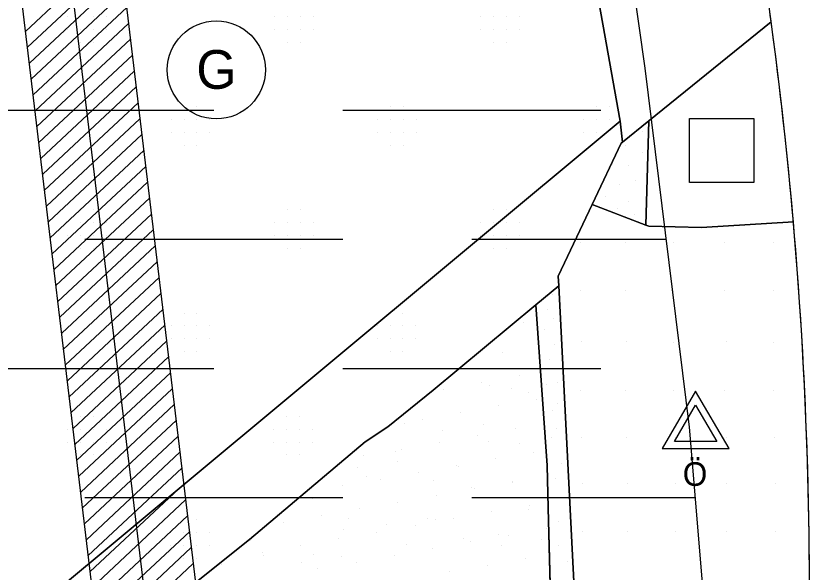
# Model space of a CAD drawing. Extents: x 409341 to 428634, y 4447481 to 4463281.
# Drawn here: x 420055.7 to 420363.5, y 4458027.9 to 4458243.5 of the extents above; entities that cross this region are included whole.
import ezdxf

# ---------------------------------------------------------------- set-up
doc = ezdxf.new("R2010")
doc.units = 0
for name, color, linetype in [('ADA', 7, 'Continuous'), ('ADAKENARI', 7, 'Continuous'), ('Default', 7, 'Continuous'), ('KALDIRIM', 7, 'Continuous'), ('LJ_SEMBOL', 7, 'Continuous'), ('PL_AYA_PARK_DINLENME', 7, 'Continuous'), ('PL_EĞİTİM', 7, 'Continuous'), ('PL_K_AKARYAKIT_LPG_Y', 7, 'Continuous'), ('PL_K_K_D_K_C_A', 7, 'Continuous'), ('PL_T_GUNUBIRLIK', 7, 'Continuous'), ('SEMBOL', 7, 'Continuous'), ('SN_TASKIN', 7, 'Continuous'), ('SN_TR_TASKIN', 7, 'Continuous'), ('TA_ENH_154', 7, 'Continuous'), ('TA_ENH_KORUMA', 7, 'Continuous'), ('TA_ENH_TARAMA', 7, 'Continuous'), ('TR_AKARYAKIT_SERVİS', 7, 'Continuous'), ('TR_BAKIMAKARYAKIT', 7, 'Continuous'), ('TR_EĞİTİM', 7, 'Continuous'), ('TR_KONUTDISIKCA', 7, 'Continuous'), ('TR_PARKALANI', 7, 'Continuous'), ('TR_TURIZM', 7, 'Continuous')]:
    doc.layers.add(name, color=color, linetype=linetype)

# ---------------------------------------------------------------- blocks, each defined once
blk = doc.blocks.new('POINT_DISPLAY')
at = {"layer": 'Default'}
blk.add_line((0, 0), (0, 0), dxfattribs=at)

msp = doc.modelspace()

# ---------------------------------------------------------------- linework, layer by layer
at = {"layer": 'ADA'}
for p, q in [((420289.84, 4458202.73), (420262.42, 4458356.84)), ((420289.84, 4458202.73), (420054.04, 4458006.23)), ((420290.78, 4458194.57), (420289.84, 4458202.73))]:
    msp.add_line(p, q, dxfattribs=at)
at = {"layer": 'ADAKENARI'}
for p, q in [((420300.95, 4458202.79), (420348.42, 4458241.16)), ((420290.78, 4458194.57), (420300.95, 4458202.79)), ((420300.95, 4458202.79), (420299.88, 4458162.44)), ((420279.04, 4458170.41), (420290.28, 4458194.16)), ((420290.28, 4458194.16), (420290.78, 4458194.57)), ((420299.88, 4458162.44), (420279.04, 4458170.41))]:
    msp.add_line(p, q, dxfattribs=at)
for points in [[(420279.04, 4458170.41), (420265.92, 4458142.64), (420273.08, 4458001.35), (420328.98, 4457995.17), (420362.93, 4457988.11)], [(420299.88, 4458162.44), (420301, 4458162.02), (420321.4, 4458161.48), (420357.02, 4458163.71)], [(420257.25, 4458131.54), (420266.1, 4458138.91)], [(420016.48, 4457954.29), (420055.68, 4457954.88), (420067.57, 4457974.09), (420078.76, 4457985.69), (420086.67, 4457992.9), (420092.78, 4457997.85), (420146.22, 4458040.56), (420191.1, 4458078.42), (420199.8, 4458084.26), (420217.45, 4458098.42), (420257.25, 4458131.54)], [(420140.13, 4457983.98), (420152.2, 4457903.36), (420230.46, 4457896.72), (420265.95, 4457891.84), (420263.49, 4457993.09), (420262.04, 4458052.83), (420261.63, 4458069.31), (420257.25, 4458131.54)]]:
    msp.add_lwpolyline(points, dxfattribs=at)
msp.add_arc((418713.25, 4458020.48), 1650, 356.27481, 10.61036, dxfattribs=at)
at = {"layer": 'KALDIRIM'}
msp.add_arc((418710.91, 4458046.13), 1668.19, 355.40061, 10.30342, dxfattribs=at)
msp.add_arc((418710.91, 4458046.13), 1668.19, 355.40061, 10.30342, dxfattribs=at)
at = {"layer": 'LJ_SEMBOL'}
for points in [[(420332.08, 4458075.78), (420319.14, 4458098.1), (420306.2, 4458075.78), (420332.08, 4458075.78)], [(420319.14, 4458092.62), (420327.31, 4458078.53), (420310.97, 4458078.53), (420319.14, 4458092.62)]]:
    msp.add_lwpolyline(points, dxfattribs=at)
msp.add_circle((420133.39, 4458222.56), 19, dxfattribs=at)
at = {"layer": 'PL_AYA_PARK_DINLENME'}
for points in [[(420300.95, 4458202.79), (420290.78, 4458194.57), (420290.28, 4458194.16), (420279.04, 4458170.41), (420299.88, 4458162.44), (420300.95, 4458202.79)], [(420263.35, 4457998.86), (420268, 4458006.76), (420273.08, 4458001.35), (420266.1, 4458138.91), (420257.25, 4458131.54), (420261.63, 4458069.31), (420262.04, 4458052.83), (420263.35, 4457998.86)], [(420041.95, 4457909.49), (420140.13, 4457983.98), (420173.45, 4458009.25), (420263.49, 4457993.09), (420262.04, 4458052.83), (420261.63, 4458069.31), (420257.25, 4458131.54), (420217.45, 4458098.42), (420199.8, 4458084.26), (420191.1, 4458078.42), (420146.22, 4458040.56), (420092.78, 4457997.85), (420086.67, 4457992.9), (420078.76, 4457985.69), (420067.57, 4457974.09), (420055.68, 4457954.88)]]:
    msp.add_lwpolyline(points, dxfattribs=at)
at = {"layer": 'PL_EĞİTİM'}
msp.add_lwpolyline([(420357.02, 4458163.71), (420321.4, 4458161.48), (420301, 4458162.02), (420299.88, 4458162.44), (420279.04, 4458170.41), (420265.92, 4458142.64), (420266.1, 4458138.91), (420273.08, 4458001.35), (420328.98, 4457995.17), (420362.93, 4457988.11)], dxfattribs=at)
msp.add_arc((418713.25, 4458020.48), 1650, 358.87612, 4.9802, dxfattribs=at)
at = {"layer": 'PL_K_AKARYAKIT_LPG_Y'}
msp.add_lwpolyline([(420348.42, 4458241.16), (420300.95, 4458202.79), (420299.88, 4458162.44), (420301, 4458162.02), (420321.4, 4458161.48), (420357.02, 4458163.71)], dxfattribs=at)
msp.add_arc((418713.25, 4458020.48), 1650, 4.9802, 7.68618, dxfattribs=at)
at = {"layer": 'PL_K_K_D_K_C_A'}
msp.add_lwpolyline([(420316.66, 4458345.69), (420283.58, 4458352.48), (420269.74, 4458355.33), (420262.42, 4458356.83), (420289.84, 4458202.73), (420290.78, 4458194.57), (420300.95, 4458202.79), (420348.42, 4458241.16)], dxfattribs=at)
msp.add_arc((418713.25, 4458020.48), 1650, 7.68618, 10.61036, dxfattribs=at)
at = {"layer": 'PL_T_GUNUBIRLIK'}
for points in [[(419982.64, 4458263.95), (419975.93, 4458193.68), (419960.88, 4458078.13), (419972.62, 4458024.38), (419969.49, 4457970.49), (420016.48, 4457954.29), (420019.94, 4457954.34), (420054.04, 4458006.23), (420289.84, 4458202.73), (420262.42, 4458356.83)], [(420266.1, 4458138.91), (420265.92, 4458142.64), (420279.04, 4458170.41), (420290.28, 4458194.16), (420290.78, 4458194.57), (420289.84, 4458202.73), (420054.04, 4458006.23), (420019.94, 4457954.34), (420055.68, 4457954.88), (420067.57, 4457974.09), (420078.76, 4457985.69), (420086.67, 4457992.9), (420092.78, 4457997.85), (420146.22, 4458040.56), (420191.1, 4458078.42), (420199.8, 4458084.26), (420217.45, 4458098.42), (420257.25, 4458131.54), (420266.1, 4458138.91)]]:
    msp.add_lwpolyline(points, dxfattribs=at)
at = {"layer": 'SN_TASKIN'}
msp.add_lwpolyline([(420197.94, 4458669), (420247.23, 4458545.81), (420267.97, 4458440.61), (420287.73, 4458306.27), (420299.5, 4458223.24), (420316.66, 4458084.14), (420330.5, 4457918.41), (420304.2, 4457786)], dxfattribs=at)
at = {"layer": 'SN_TR_TASKIN'}
for p, q in [((420032.43, 4458206.9), (420132.43, 4458206.9)), ((420182.43, 4458206.9), (420282.43, 4458206.9)), ((420082.43, 4458156.9), (420182.43, 4458156.9)), ((420232.43, 4458156.9), (420307.69, 4458156.9)), ((420032.43, 4458106.9), (420132.43, 4458106.9)), ((420182.43, 4458106.9), (420282.43, 4458106.9)), ((420082.43, 4458056.9), (420182.43, 4458056.9)), ((420232.43, 4458056.9), (420318.94, 4458056.9))]:
    msp.add_line(p, q, dxfattribs=at)
at = {"layer": 'TA_ENH_154'}
msp.add_lwpolyline([(420133.44, 4457787.81), (420133.21, 4457789.61), (420077.71, 4458253.32), (420056.56, 4458429.96)], dxfattribs=at)
at = {"layer": 'TA_ENH_KORUMA'}
msp.add_line((420113.26, 4457788.02), (420057.85, 4458250.94), dxfattribs=at)
msp.add_lwpolyline([(419911.21, 4459796.11), (420008.03, 4459521.93), (419970.44, 4459317.8), (420039.72, 4458738.96), (420097.57, 4458255.69), (420153.07, 4457792.04), (420153.62, 4457787.59)], dxfattribs=at)
at = {"layer": 'TA_ENH_TARAMA'}
for p, q in [((420059.46, 4458237.49), (420095.69, 4458271.35)), ((420060.19, 4458231.33), (420096.43, 4458265.2)), ((420060.93, 4458225.18), (420097.17, 4458259.04)), ((420061.67, 4458219.02), (420097.9, 4458252.89)), ((420062.4, 4458212.87), (420098.64, 4458246.73)), ((420063.14, 4458206.71), (420099.38, 4458240.57)), ((420063.88, 4458200.56), (420100.11, 4458234.42)), ((420064.61, 4458194.4), (420100.85, 4458228.26)), ((420065.35, 4458188.24), (420101.59, 4458222.11)), ((420066.09, 4458182.09), (420102.32, 4458215.95)), ((420066.82, 4458175.93), (420103.06, 4458209.8)), ((420067.56, 4458169.78), (420103.8, 4458203.64)), ((420068.3, 4458163.62), (420104.53, 4458197.49)), ((420069.03, 4458157.47), (420105.27, 4458191.33)), ((420069.77, 4458151.31), (420106.01, 4458185.17)), ((420070.51, 4458145.16), (420106.74, 4458179.02)), ((420071.24, 4458139), (420107.48, 4458172.86)), ((420071.98, 4458132.84), (420108.22, 4458166.71)), ((420072.72, 4458126.69), (420108.95, 4458160.55)), ((420073.46, 4458120.53), (420109.69, 4458154.4)), ((420074.19, 4458114.38), (420110.43, 4458148.24)), ((420074.93, 4458108.22), (420111.17, 4458142.09)), ((420075.67, 4458102.07), (420111.9, 4458135.93)), ((420076.4, 4458095.91), (420112.64, 4458129.77)), ((420077.14, 4458089.76), (420113.38, 4458123.62)), ((420077.88, 4458083.6), (420114.11, 4458117.46)), ((420078.61, 4458077.44), (420114.85, 4458111.31)), ((420079.35, 4458071.29), (420115.59, 4458105.15)), ((420080.09, 4458065.13), (420116.32, 4458099)), ((420080.82, 4458058.98), (420117.06, 4458092.84)), ((420081.56, 4458052.82), (420117.8, 4458086.68)), ((420082.3, 4458046.67), (420118.53, 4458080.53)), ((420083.03, 4458040.51), (420119.27, 4458074.37)), ((420083.77, 4458034.36), (420120.01, 4458068.22)), ((420084.51, 4458028.2), (420120.74, 4458062.06)), ((420085.24, 4458022.04), (420121.48, 4458055.91)), ((420085.98, 4458015.89), (420122.22, 4458049.75)), ((420086.72, 4458009.73), (420122.95, 4458043.6)), ((420087.45, 4458003.58), (420123.69, 4458037.44)), ((420088.19, 4457997.42), (420124.43, 4458031.28))]:
    msp.add_line(p, q, dxfattribs=at)
at = {"layer": 'TR_AKARYAKIT_SERVİS'}
for points in [[(420348.42, 4458241.16), (420300.95, 4458202.79), (420299.88, 4458162.44), (420301, 4458162.02), (420321.4, 4458161.48), (420357.02, 4458163.71)], [(420316.83, 4458178.92), (420316.83, 4458203.69), (420341.71, 4458203.69), (420341.71, 4458178.92), (420316.83, 4458178.92)]]:
    msp.add_lwpolyline(points, dxfattribs=at)
msp.add_arc((418713.25, 4458020.48), 1650, 4.9802, 7.68618, dxfattribs=at)
at = {"layer": 'TR_BAKIMAKARYAKIT'}
msp.add_line((420349.34, 4458233.74), (420349.36, 4458233.74), dxfattribs=at)
at = {"layer": 'TR_KONUTDISIKCA'}
for points in [[(420316.66, 4458345.69), (420283.58, 4458352.48), (420269.74, 4458355.33), (420262.42, 4458356.83), (420289.84, 4458202.73), (420290.78, 4458194.57), (420300.95, 4458202.79)], [(420316.66, 4458345.69), (420283.58, 4458352.48), (420269.74, 4458355.33), (420262.42, 4458356.83), (420289.84, 4458202.73), (420290.78, 4458194.57)], [(420290.78, 4458194.57), (420300.95, 4458202.79), (420348.42, 4458241.16)], [(420300.95, 4458202.79), (420348.42, 4458241.16)]]:
    msp.add_lwpolyline(points, dxfattribs=at)
msp.add_arc((418713.25, 4458020.48), 1650, 7.68618, 10.61036, dxfattribs=at)
msp.add_arc((418713.25, 4458020.48), 1650, 7.68618, 10.61036, dxfattribs=at)

# ---------------------------------------------------------------- block references
at = {"layer": 'TR_EĞİTİM', "xscale": 0.1, "yscale": 0.10000000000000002}
for p in [(420274.55, 4458155.63), (420291.91, 4458155.8), (420310.72, 4458155.58), (420330.47, 4458155.8), (420349.27, 4458155.58), (420274.55, 4458137.04), (420291.91, 4458137.22), (420310.72, 4458137), (420330.47, 4458137.22), (420349.27, 4458137), (420274.99, 4458117.13), (420292.36, 4458117.31), (420310.72, 4458117), (420330.92, 4458117.31), (420349.27, 4458117), (420274.55, 4458098.33), (420291.91, 4458098.51), (420310.72, 4458098.28), (420330.47, 4458098.51), (420349.27, 4458098.28), (420275, 4458080.12), (420292.37, 4458080.29), (420311.17, 4458080.07), (420330.93, 4458080.29), (420349.73, 4458080.07), (420275.23, 4458062.22), (420292.59, 4458062.4), (420311.4, 4458062.17), (420331.15, 4458062.4), (420349.95, 4458062.17), (420275.23, 4458043.64), (420292.59, 4458043.81), (420311.4, 4458043.59), (420331.15, 4458043.81), (420349.95, 4458043.59)]:
    msp.add_blockref('POINT_DISPLAY', p, dxfattribs=at)
at = {"layer": 'TR_PARKALANI', "xscale": 0.1, "yscale": 0.10000000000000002}
for p in [(420298.51, 4458198.57), (420292.07, 4458193.33), (420298.51, 4458190.63), (420286.98, 4458185.84), (420293.12, 4458185.39), (420289.53, 4458178.05), (420295.97, 4458179.55), (420284.29, 4458173.56), (420293.12, 4458171.61), (420288.93, 4458168.76), (420295.52, 4458166.37), (420263.62, 4458135.36), (420261.82, 4458129.82), (420264.22, 4458126.08), (420252.43, 4458124.53), (420252.43, 4458124.53), (420242.89, 4458119.79), (420260.62, 4458121.88), (420264.37, 4458116.04), (420244.31, 4458112.95), (420244.31, 4458112.95), (420262.42, 4458110.35), (420250.97, 4458103.97), (420250.97, 4458103.97), (420236.2, 4458101.36), (420236.2, 4458101.36), (420265.71, 4458101.37), (420221.43, 4458098.76), (420221.43, 4458098.76), (420239.42, 4458100.09), (420247.73, 4458098.98), (420247.73, 4458098.98), (420261.22, 4458100.47), (420254.19, 4458097.48), (420257.64, 4458094.99), (420257.64, 4458094.99), (420242.86, 4458092.38), (420242.86, 4458092.38), (420265.71, 4458093.28), (420228.09, 4458089.78), (420228.09, 4458089.78), (420263.77, 4458090.58), (420206.4, 4458085.6), (420213.32, 4458087.17), (420213.32, 4458087.17), (420236.81, 4458085.32), (420221.17, 4458083), (420249.52, 4458083.4), (420249.52, 4458083.4), (420265.41, 4458083.54), (420234.75, 4458080.8), (420234.75, 4458080.8), (420263.32, 4458079.95), (420219.98, 4458078.19), (420219.98, 4458078.19), (420238.83, 4458078.47), (420250.71, 4458077.79), (420203, 4458074.5), (420205.21, 4458075.59), (420205.21, 4458075.59), (420256.18, 4458074.42), (420256.18, 4458074.42), (420190.44, 4458072.98), (420190.44, 4458072.98), (420203.79, 4458070.83), (420241.41, 4458071.82), (420241.41, 4458071.82), (420267.21, 4458070.21), (420188.15, 4458068.51), (420226.64, 4458069.21), (420226.64, 4458069.21), (420227.34, 4458068.83), (420227.34, 4458068.83), (420191.51, 4458064.86), (420191.51, 4458064.86), (420197.1, 4458064), (420197.1, 4458064), (420211.87, 4458066.61), (420211.87, 4458066.61), (420264.81, 4458064.07), (420269.61, 4458066.02), (420182.32, 4458061.4), (420182.32, 4458061.4), (420217.7, 4458063.3), (420232.47, 4458060.7), (420248.07, 4458062.84), (420248.07, 4458062.84), (420248.11, 4458063.02), (420218.53, 4458057.63), (420218.53, 4458057.63), (420233.3, 4458060.23), (420233.3, 4458060.23), (420170.78, 4458056.34), (420203.76, 4458055.02), (420203.76, 4458055.02), (420263.92, 4458056.58), (420188.98, 4458052.42), (420188.98, 4458052.42), (420254.29, 4458052.27), (420254.73, 4458053.86), (420254.73, 4458053.86), (420174.21, 4458049.81), (420174.21, 4458049.81), (420184.68, 4458048.81), (420215.09, 4458048.53), (420225.19, 4458048.65), (420225.19, 4458048.65), (420239.96, 4458051.25), (420239.96, 4458051.25), (420159.44, 4458047.21), (420159.44, 4458047.21), (420199.45, 4458046.21), (420210.42, 4458046.04), (420210.42, 4458046.04), (420218.45, 4458048.31), (420266.16, 4458047.45), (420182.61, 4458044.35), (420195.64, 4458043.44), (420195.64, 4458043.44), (420242.8, 4458042.63), (420242.8, 4458042.63), (420246.62, 4458042.27), (420246.62, 4458042.27), (420261.39, 4458044.88), (420261.39, 4458044.88), (420146.78, 4458040.38), (420180.87, 4458040.83), (420180.87, 4458040.83), (420229, 4458041), (420231.85, 4458039.67), (420231.85, 4458039.67), (420259.41, 4458040.72), (420166.1, 4458038.23), (420166.1, 4458038.23), (420206.96, 4458038.67), (420206.96, 4458038.67), (420217.08, 4458037.06), (420217.08, 4458037.06), (420243.77, 4458038.4), (420265.86, 4458038.16), (420136.56, 4458033.02), (420136.56, 4458033.02), (420151.33, 4458035.62), (420151.33, 4458035.62), (420151.66, 4458034.33), (420171.12, 4458034.7), (420171.12, 4458034.7), (420182.08, 4458034.04), (420202.31, 4458034.46), (420202.31, 4458034.46), (420253.28, 4458033.29), (420253.28, 4458033.29), (420135.28, 4458030.74), (420135.28, 4458030.74), (420166.43, 4458031.72), (420187.53, 4458031.85), (420187.53, 4458031.85), (420238.51, 4458030.69), (420238.51, 4458030.69), (420269.31, 4458032.02), (420172.76, 4458029.25), (420172.76, 4458029.25), (420223.74, 4458028.08), (420223.74, 4458028.08)]:
    msp.add_blockref('POINT_DISPLAY', p, dxfattribs=at)
at = {"layer": 'TR_TURIZM', "xscale": 0.1, "yscale": 0.10000000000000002}
for p in [(420075.88, 4458243.33), (420080.88, 4458243.33), (420085.88, 4458243.33), (420090.88, 4458243.33), (420155.88, 4458243.33), (420160.88, 4458243.33), (420165.88, 4458243.33), (420170.88, 4458243.33), (420235.88, 4458243.33), (420240.88, 4458243.33), (420245.88, 4458243.33), (420250.88, 4458243.33), (420075.88, 4458238.33), (420080.88, 4458238.33), (420085.88, 4458238.33), (420090.88, 4458238.33), (420155.88, 4458238.33), (420160.88, 4458238.33), (420165.88, 4458238.33), (420170.88, 4458238.33), (420235.88, 4458238.33), (420240.88, 4458238.33), (420245.88, 4458238.33), (420250.88, 4458238.33), (420080.88, 4458233.33), (420085.88, 4458233.33), (420160.88, 4458233.33), (420165.88, 4458233.33), (420240.88, 4458233.33), (420245.88, 4458233.33), (420120.88, 4458208.33), (420125.88, 4458208.33), (420200.88, 4458208.33), (420205.88, 4458208.33), (420280.71, 4458208.34), (420285.71, 4458208.34), (420115.88, 4458203.33), (420120.88, 4458203.33), (420125.88, 4458203.33), (420130.88, 4458203.33), (420195.88, 4458203.33), (420200.88, 4458203.33), (420205.88, 4458203.33), (420210.88, 4458203.33), (420275.71, 4458203.34), (420280.71, 4458203.34), (420285.71, 4458203.34), (420115.88, 4458198.33), (420120.88, 4458198.33), (420125.88, 4458198.33), (420130.88, 4458198.33), (420195.88, 4458198.33), (420200.88, 4458198.33), (420205.88, 4458198.33), (420210.88, 4458198.33), (420275.71, 4458198.34), (420280.71, 4458198.34), (420120.88, 4458193.33), (420125.88, 4458193.33), (420200.88, 4458193.33), (420205.88, 4458193.33), (420080.88, 4458168.33), (420085.88, 4458168.33), (420160.88, 4458168.33), (420165.88, 4458168.33), (420240.71, 4458168.34), (420245.71, 4458168.34), (420075.88, 4458163.33), (420080.88, 4458163.33), (420085.88, 4458163.33), (420090.88, 4458163.33), (420155.88, 4458163.33), (420160.88, 4458163.33), (420165.88, 4458163.33), (420170.88, 4458163.33), (420235.71, 4458163.34), (420240.71, 4458163.34), (420245.71, 4458163.34), (420250.71, 4458163.34), (420075.88, 4458158.33), (420080.88, 4458158.33), (420085.88, 4458158.33), (420090.88, 4458158.33), (420155.88, 4458158.33), (420160.88, 4458158.33), (420165.88, 4458158.33), (420170.88, 4458158.33), (420235.71, 4458158.34), (420240.71, 4458158.34), (420245.71, 4458158.34), (420250.71, 4458158.34), (420080.88, 4458153.33), (420085.88, 4458153.33), (420160.88, 4458153.33), (420165.88, 4458153.33), (420240.71, 4458153.34), (420245.71, 4458153.34), (420120.88, 4458128.33), (420125.88, 4458128.33), (420200.71, 4458128.34), (420205.71, 4458128.34), (420115.88, 4458123.33), (420120.88, 4458123.33), (420125.88, 4458123.33), (420130.88, 4458123.33), (420195.71, 4458123.34), (420200.71, 4458123.34), (420205.71, 4458123.34), (420210.71, 4458123.34), (420115.88, 4458118.33), (420120.88, 4458118.33), (420125.88, 4458118.33), (420130.88, 4458118.33), (420195.71, 4458118.34), (420200.71, 4458118.34), (420205.71, 4458118.34), (420210.71, 4458118.34), (420120.88, 4458113.33), (420125.88, 4458113.33), (420200.71, 4458113.34), (420205.71, 4458113.34), (420080.88, 4458088.33), (420085.88, 4458088.33), (420160.71, 4458088.34), (420165.71, 4458088.34), (420075.88, 4458083.33), (420080.88, 4458083.33), (420085.88, 4458083.33), (420090.88, 4458083.33), (420155.71, 4458083.34), (420160.71, 4458083.34), (420165.71, 4458083.34), (420170.71, 4458083.34), (420075.88, 4458078.33), (420080.88, 4458078.33), (420085.88, 4458078.33), (420090.88, 4458078.33), (420155.71, 4458078.34), (420160.71, 4458078.34), (420165.71, 4458078.34), (420170.71, 4458078.34), (420080.88, 4458073.33), (420085.88, 4458073.33), (420160.71, 4458073.34), (420165.71, 4458073.34), (420120.71, 4458048.34), (420125.71, 4458048.34), (420115.71, 4458043.34), (420120.71, 4458043.34), (420125.71, 4458043.34), (420130.71, 4458043.34), (420115.71, 4458038.34), (420120.71, 4458038.34), (420125.71, 4458038.34), (420130.71, 4458038.34), (420120.71, 4458033.34), (420125.71, 4458033.34)]:
    msp.add_blockref('POINT_DISPLAY', p, dxfattribs=at)

# ---------------------------------------------------------------- texts
at = {"layer": 'LJ_SEMBOL'}
msp.add_text('G', height=15, dxfattribs=at).set_placement((420125.63, 4458215.23))
at = {"layer": 'SEMBOL'}
msp.add_text('Ö', height=9.17, dxfattribs=at).set_placement((420314.14, 4458061.36))

doc.saveas('drawing.dxf')
